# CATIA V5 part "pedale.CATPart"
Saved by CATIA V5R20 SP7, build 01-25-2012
Part number: pedale
Bounding box of the stored display mesh (mm): x -37.853 to 130.826, y -140 to 140, z -216.932 to 141.275
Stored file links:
  D:\thinkmotion-MPB\Dropbox\Pack 1 sylvain\CFAO_2010_yyang\yyang\CFAO_2010_yyang\pedale.CATPart
  D:\thinkmotion-MPB\Dropbox\Pack 1 sylvain\CFAO_2010_yyang\yyang\CFAO_2010_yyang\yyang.CATProduct
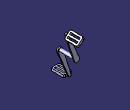
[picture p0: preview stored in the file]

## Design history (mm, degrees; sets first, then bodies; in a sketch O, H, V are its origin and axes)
External parameters (linked from other documents)
  `External.rayon de la liaison du petale` = 10 mm
  `External.Longueur de la liaison` = 47.5 mm
  `External.Longueur du pedale` = 175 mm
Set1
  Plane1: linked copy from another document
  Point1: linked copy from another document
Set2
  Plane2: type Offset, RefPlane Plane1, Offset 0
  Line1: type PtDir, RefPoint Point1, Direction (1, 0, 0), Start 0, End 20
  Line2: type Angle, RefPoint Point1, Curve Line1, Support Plane2, Start 0, End 20, Angle 20
Body1 (main body)
  Sketch1 on Plane1, origin (0, 0, 0), H (-1, 0, 0), V (0, 0, 1)
    circle A1 centre (-47.0008, -44.9861) radius 10
    point P1 (-47.0008, -44.9861)
    reference projected point E1 (-47.0008, -44.9861) from Point1
    reference projected point E2 (-47.0008, -44.9861) from Point1
    distance A1 E2 = 10 {= `External.rayon de la liaison du petale`}
    coincidence: P1 E1
  Pad1: profile Sketch1, direction (0, 1, 0), length 47.5 {= `External.Longueur de la liaison`}, mirrored extent
  Sketch2 on start face of Pad1, origin (0, -47.5, 0), H (1, 0, 0), V (0, 0, 1)
    arc A1 centre (47.0008, -44.9861) radius 15 from (60.8634, -50.7158) to (32.6985, -40.4646) ccw
    point P1 (47.0008, -44.9861)
    reference projected point E1 (47.0008, -44.9861) from Point1
    reference projected point E2 (47.0008, -44.9861) from Point1
    axis line L1 (47.0008, -44.9861) -> (-12.8527, -209.4323)
    arc A2 centre (-12.8527, -209.4323) radius 7.5 from (-20.0039, -207.1716) to (-5.9214, -212.2972) ccw
    line L2 (32.6985, -40.4646) -> (-20.0039, -207.1716)
    line L3 (60.8634, -50.7158) -> (-5.9214, -212.2972)
    distance A1 E2 = 15
    angle L1 V = 160
    length L1 = 175 {= `External.Longueur du pedale`}
    radius A2 = 7.5
    coincidence: P1 E1
    tangency: L2 A2, L3 A2, L3 A1, L2 A1
  Pad2: profile Sketch2, direction (0, -1, 0), length 7.5
  Sketch3 on end face of Pad2, origin (0, -55, 0), H (1, 0, 0), V (0, 0, 1)
    circle A1 centre (-12.8527, -209.4323) radius 5
    point P1 (-12.8527, -209.4323)
    reference projected arc E1 centre (-12.8527, -209.4323) radius 7.5 from (-20.0039, -207.1716) to (-5.9214, -212.2972) ccw from edge [face of Pad2 from Sketch2.A2 | end face of Pad2]
    distance A1 P1 = 5 {= 5mm}
    concentricity: P1 E1
  Pad3: profile Sketch3, direction (0, -1, 0), length 5
  Sketch4 on end face of Pad3, origin (0, -60, 0), H (1, 0, 0), V (0, 0, 1)
    line L1 (-37.8527, -201.9323) -> (12.1473, -201.9323)
    line L2 (12.1473, -201.9323) -> (12.1473, -216.9323)
    line L3 (12.1473, -216.9323) -> (-37.8527, -216.9323)
    line L4 (-37.8527, -216.9323) -> (-37.8527, -201.9323)
    reference projected circle E1 centre (-12.8527, -209.4323) radius 5 from edge [face of Pad3 from Sketch3.A1 | end face of Pad3]
    reference projected circle E2 centre (-12.8527, -209.4323) radius 5 from edge [face of Pad3 from Sketch3.A1 | end face of Pad3]
    length L2 = 15
    length L3 = 50
    distance E1 L2 = 20
    distance E2 L3 = 2.5
    perpendicularity: L2 L3, L2 L1, L4 L1
  Pad4: profile Sketch4, direction (0, -1, 0), length 80
  Sketch5 on face of Pad4 from Sketch4.L1, origin (0, 0, -201.9323), H (1, 0, 0), V (0, 1, 0)
    line L1 (-27.8527, -70) -> (-17.8527, -70)
    line L2 (-17.8527, -70) -> (-17.8527, -130)
    line L3 (-17.8527, -130) -> (-27.8527, -130)
    line L4 (-27.8527, -130) -> (-27.8527, -70)
    point P5 (-7.8527, -70)
    line L5 (-7.8527, -70) -> (2.1473, -70)
    line L6 (2.1473, -70) -> (2.1473, -130)
    line L7 (2.1473, -130) -> (-7.8527, -130)
    line L8 (-7.8527, -130) -> (-7.8527, -70)
    point P7 (2.1473, -130)
    reference projected line E1 (29.2483, -60) -> (-20.7517, -60) from edge [start face of Pad4 | face of Pad4 from Sketch4.L1]
    reference projected line E2 (29.2483, -140) -> (-20.7517, -140) from edge [face of Pad4 from Sketch4.L1 | end face of Pad4]
    reference projected line E3 (-37.8527, -62.5) -> (-37.8527, -142.5) from edge [face of Pad4 from Sketch4.L4 | face of Pad4 from Sketch4.L1]
    reference projected line E4 (12.1473, -62.5) -> (12.1473, -142.5) from edge [face of Pad4 from Sketch4.L1 | face of Pad4 from Sketch4.L2]
    distance L1 E1 = 10
    distance L3 E2 = 10
    distance E3 L4 = 10
    distance L6 E4 = 10
    length L1 = 10
    length L5 = 10
    horizontal: L1 H, L3 H, L5 H, L7 H
    vertical: L2 V, L4 V, L6 V, L8 V
    coincidence: P5 L1, P7 L3
  Pocket1: profile Sketch5, direction (0, 0, -1), up to face of Pad4 from Sketch4.L3
  Chamfer1: length 5, angle 60, on edge [face of Pad4 from Sketch4.L2 | end face of Pad4]; edge [face of Pad4 from Sketch4.L4 | end face of Pad4]; edge [start face of Pad4 | face of Pad4 from Sketch4.L4]; edge [start face of Pad4 | face of Pad4 from Sketch4.L2]
  CircPattern1: of Pad2, Sketch2, Pad3, Sketch3, Pad4, Sketch4, Pocket1, Sketch5, Chamfer1, instances 2, angular step 180, axis from Line2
